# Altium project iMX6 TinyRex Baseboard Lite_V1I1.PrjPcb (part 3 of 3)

## Sheet [12] - UARTS.SchDoc
size A3; DocumentNumber: 12; SheetNumber: 12; SheetTotal: 18
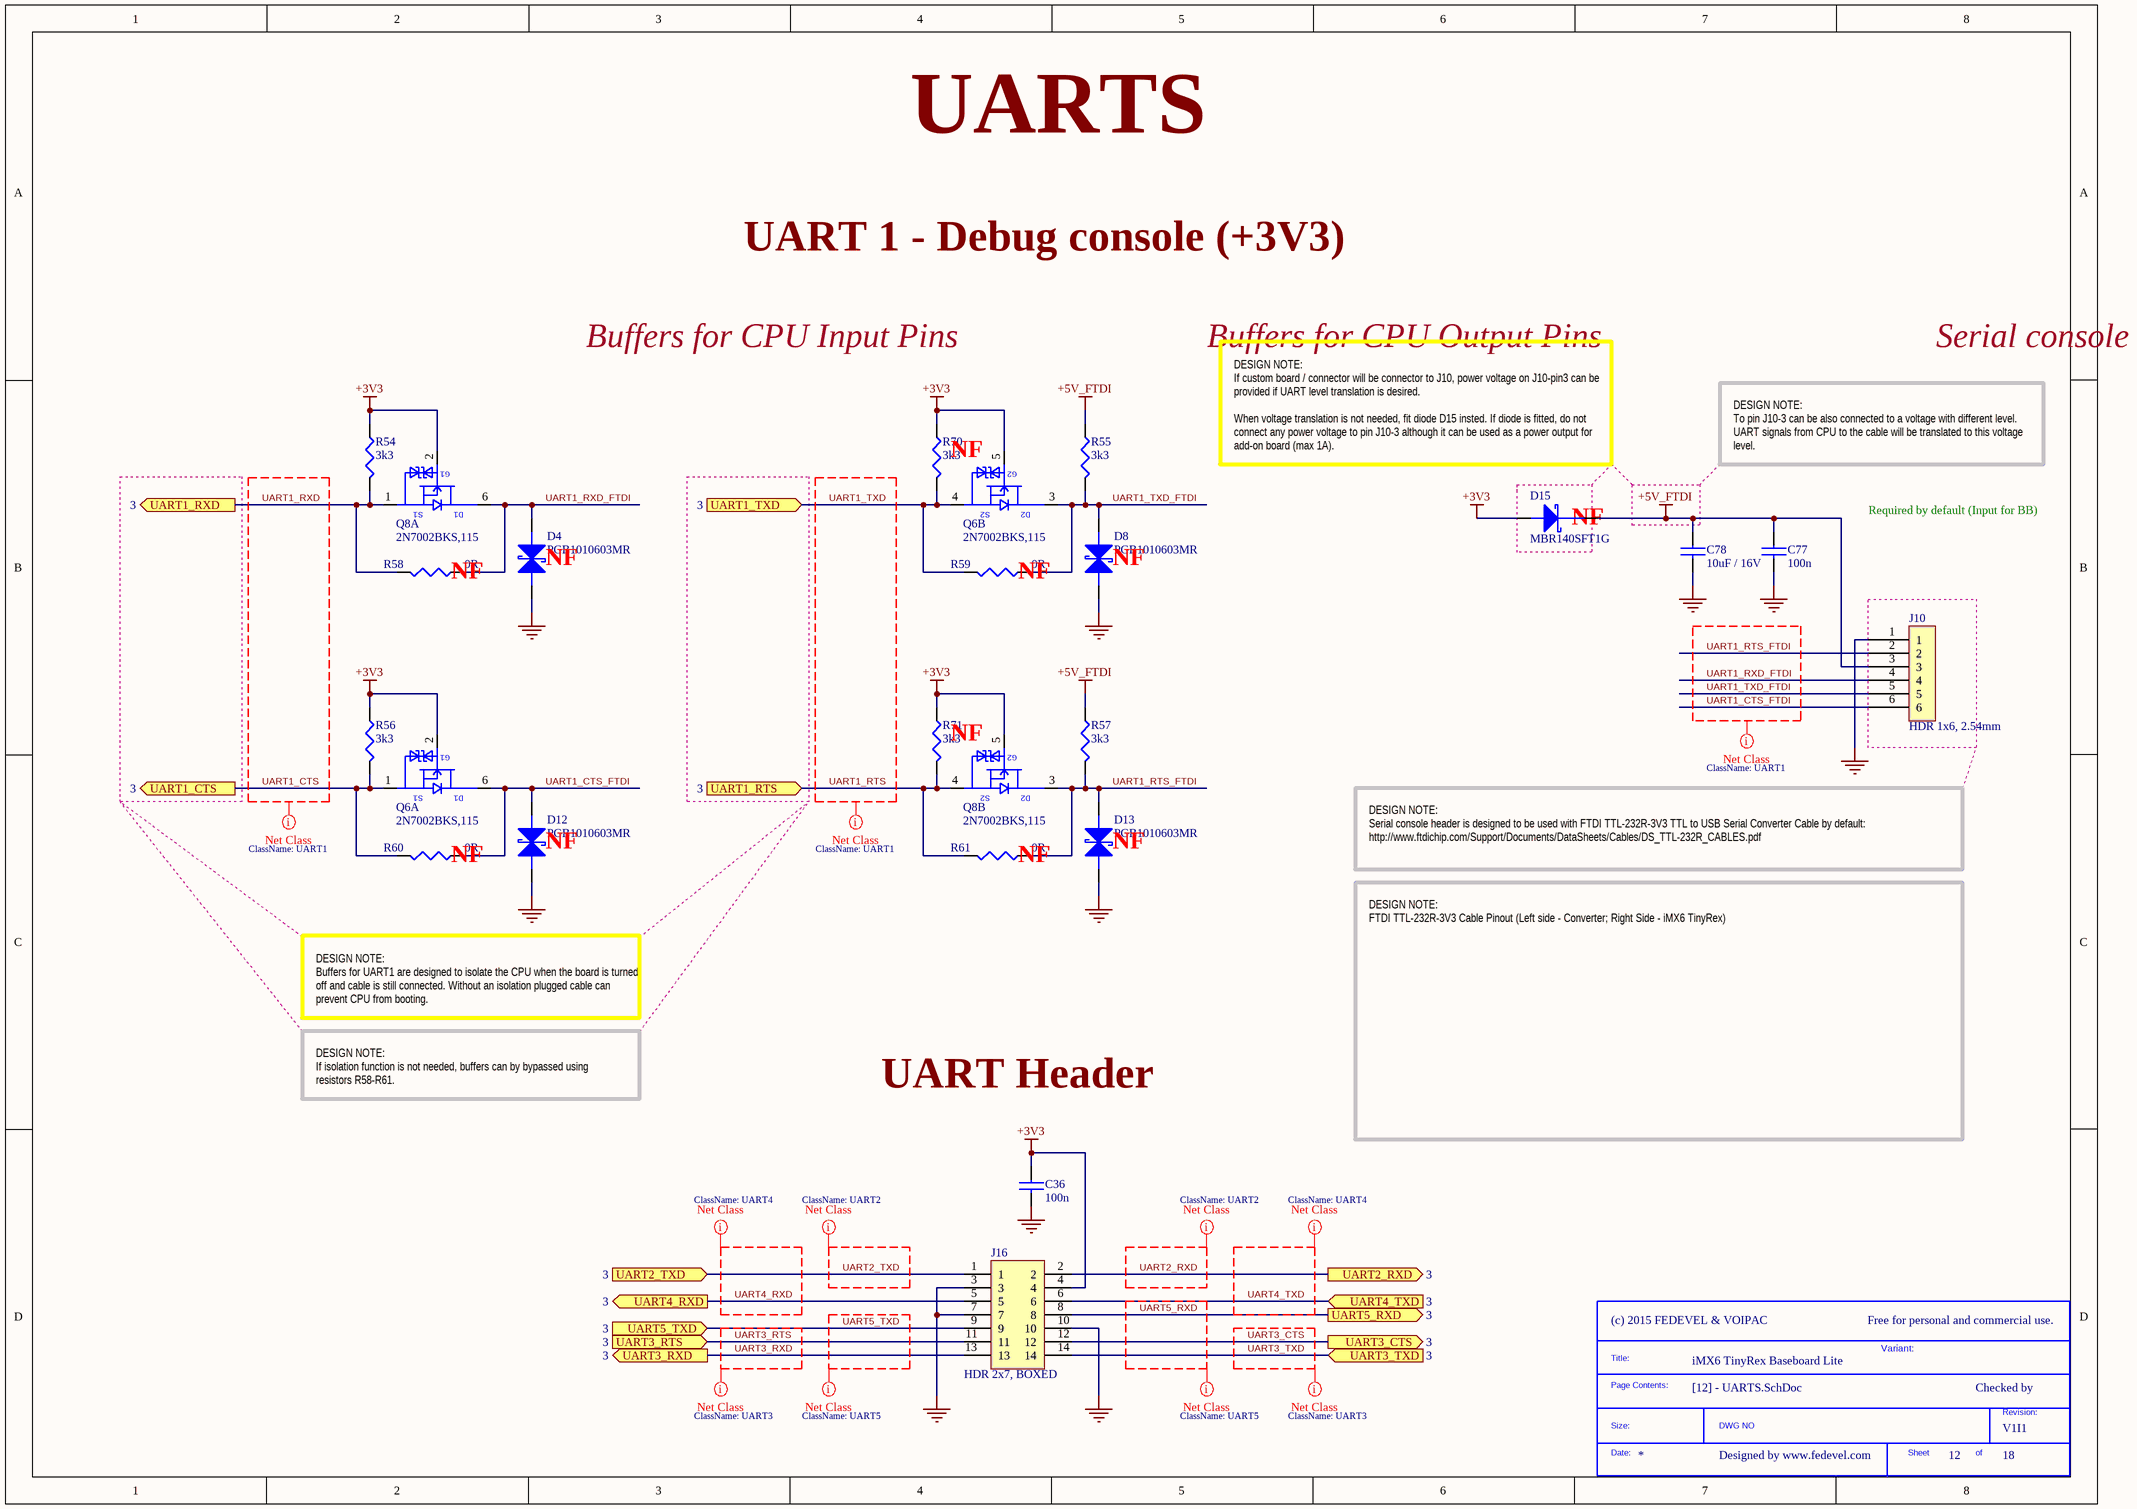
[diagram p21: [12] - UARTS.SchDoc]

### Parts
(Parts that share a designator on the sheet are numbered #1, #2 ... from top to bottom, then left to right.)
*#15  SDTitleBlock  (value not drawn)  (graphical)
C36  100n  [C0402]
C77  100n  [C0402]
C78  10uF / 16V  [C0805]
D4  PGB1010603MR  [C0603]
D8  PGB1010603MR  [C0603]
D12  PGB1010603MR  [C0603]
D13  PGB1010603MR  [C0603]
D15  MBR140SFT1G  [SOD-123FL]
J10  HDR 1x6, 2.54mm  [Hdr_1x6_2.54mm]
J16  HDR 2x7, BOXED  [HDR_2x7_2.54MM_BOXED]
Q6  2N7002BKS,115  [SOT363]  (parts A,B of 2)
Q8  2N7002BKS,115  [SOT363]  (parts A,B of 2)
R54  3k3  [R0402]
R55  3k3  [R0402]
R56  3k3  [R0402]
R57  3k3  [R0402]
R58  0R  [R0402]
R59  0R  [R0402]
R60  0R  [R0402]
R61  0R  [R0402]
R70  3k3  [R0402]
R71  3k3  [R0402]

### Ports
UART1_CTS (out, see 3), UART1_RTS (in, see 3), UART1_RXD (out, see 3), UART1_TXD (in, see 3), UART2_RXD (out, see 3), UART2_TXD (in, see 3), UART3_CTS (out, see 3), UART3_RTS (in, see 3), UART3_RXD (out, see 3), UART3_TXD (in, see 3), UART4_RXD (out, see 3), UART4_TXD (in, see 3), UART5_RXD (out, see 3), UART5_TXD (in, see 3)

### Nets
+3V3: C36.1 D15.2(Anode) J16.4 Q6.2(GATE1) Q6.5(GATE2) Q8.2(GATE1) Q8.5(GATE2) R54.2 R56.2 R70.2 R71.2
+5V_FTDI: C77.1 C78.1 D15.1(Cathode) J10.3 R55.2 R57.2
GND: C36.2 C77.2 C78.2 D4.2 D8.2 D12.2 D13.2 J10.1 J16.3 J16.7 J16.10
UART1_CTS: Q6.1(SOURCE1) R56.1 R60.1 ; port UART1_CTS
UART1_CTS_FTDI: D12.1 J10.6 Q6.6(DRAIN1) R60.2
UART1_RTS: Q8.4(SOURCE2) R61.1 R71.1 ; port UART1_RTS
UART1_RTS_FTDI: D13.1 J10.2 Q8.3(DRAIN2) R57.1 R61.2
UART1_RXD: Q8.1(SOURCE1) R54.1 R58.1 ; port UART1_RXD
UART1_RXD_FTDI: D4.1 J10.4 Q8.6(DRAIN1) R58.2
UART1_TXD: Q6.4(SOURCE2) R59.1 R70.1 ; port UART1_TXD
UART1_TXD_FTDI: D8.1 J10.5 Q6.3(DRAIN2) R55.1 R59.2
UART2_RXD: J16.2 ; port UART2_RXD
UART2_TXD: J16.1 ; port UART2_TXD
UART3_CTS: J16.12 ; port UART3_CTS
UART3_RTS: J16.11 ; port UART3_RTS
UART3_RXD: J16.13 ; port UART3_RXD
UART3_TXD: J16.14 ; port UART3_TXD
UART4_RXD: J16.5 ; port UART4_RXD
UART4_TXD: J16.6 ; port UART4_TXD
UART5_RXD: J16.8 ; port UART5_RXD
UART5_TXD: J16.9 ; port UART5_TXD

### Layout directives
net class UART3: UART3_CTS, UART3_RTS, UART3_RXD, UART3_TXD
net class UART2: UART2_RXD, UART2_TXD
net class UART5: UART5_RXD, UART5_TXD
net class UART4: UART4_RXD, UART4_TXD
net class UART1: UART1_CTS, UART1_CTS_FTDI, UART1_RTS, UART1_RTS_FTDI, UART1_RXD, UART1_RXD_FTDI, UART1_TXD, UART1_TXD_FTDI

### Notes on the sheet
- UARTS
- UART 1 - Debug console (+3V3)
- Buffers for CPU Input Pins
- Buffers for CPU Output Pins
- Serial console header
- DESIGN NOTE:
  If custom board / connector will be connector to J10, power voltage on J10-pin3 can be provided if UART level translation is desired.
  When voltage translation is not needed, fit diode D15 insted. If diode is fitted, do not connect any power voltage to pin J10-3 although it can be used as a power output for add-on board (max 1A).
- DESIGN NOTE:
  To pin J10-3 can be also connected to a voltage with different level. UART signals from CPU to the cable will be translated to this voltage level.
- Required by default (Input for BB)
- DESIGN NOTE:
  Serial console header is designed to be used with FTDI TTL-232R-3V3 TTL to USB Serial Converter Cable by default:
  http://www.ftdichip.com/Support/Documents/DataSheets/Cables/DS_TTL-232R_CABLES.pdf
- DESIGN NOTE:
  FTDI TTL-232R-3V3 Cable Pinout (Left side - Converter; Right Side - iMX6 TinyRex)
- DESIGN NOTE:
  Buffers for UART1 are designed to isolate the CPU when the board is turned off and cable is still connected. Without an isolation plugged cable can prevent CPU from booting.
- DESIGN NOTE:
  If isolation function is not needed, buffers can by bypassed using resistors R58-R61.
- UART Header
- Free for personal and commercial use.
- Variant:
- Checked by
- Designed by www.fedevel.com

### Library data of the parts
C36 C77 = C1005X5R1H104K: CAP CER .10UF 50V X5R 10% 0402; Manufacturer: TDK Corporation; Capacitance: 0.1µF; Value: 100nF; .Checked PCB: used
C78 = C2012X5R1C106M: CAP CER 10UF 16V 20% X5R 0805; Manufacturer: TDK Corporation; Manufacturer Part Number: C2012X5R1C106M/1.25; Capacitance: 10µF; .Checked PCB: used
D4 D8 D12 D13 = PGB1010603MR: SUPPRESSOR ESD 24VDC 0603 SMD; Manufacturer: Littelfuse Inc; Voltage - Reverse Standoff (Typ): 24V; Polarization: Bidirectional; .Creator: MM; .Checked PCB: used
D15 = MBR140SFT1G: DIODE SCHOTTKY 40V 1A SOD123L; Manufacturer: ON Semiconductor; Voltage - Forward (Vf) (Max) @ If: 550mV @ 1A; Speed: Fast Recovery =< 500ns, > 200mA (Io); Current - Reverse Leakage @ Vr: 500µA @ 40V; .Creator: MM
J10 = 68001-206HLF: CONN HEADER 6POS .100 STR 15AU; Manufacturer: FCI; Connector Type: Header, Unshrouded; Number of Positions: 6; Number of Positions Loaded: All; Pitch: 0.100" (2.54mm); .Creator: MM
J16 = D2514-6002-AR: CONN HEADER 14POS VERT 10GOLD; Manufacturer: 3M; Connector Type: Header, Shrouded; Number of Positions: 14; Number of Positions Loaded: All; Pitch: 0.100" (2.54mm); .Creator: MM; .Checked PCB: used
Q6 Q8 = 2N7002BKS,115: MOSFET 2N-CH 60V 0.3A 6TSSOP; Manufacturer: NXP Semiconductors; FET Type: 2 N-Channel (Dual); FET Feature: Logic Level Gate; Current - Continuous Drain (Id) @ 25°C: 300mA; Rds On (Max) @ Id, Vgs: 1.6 Ohm @ 500mA, 10V; Vgs(th) (Max) @ Id: 2.1V @ 250µA; Gate Charge (Qg) @ Vgs: 0.6nC @ 4.5V; Input Capacitance (Ciss) @ Vds: 50pF @ 10V; Power - Max: 295mW; .Creator: MM
R54-R57 R70 R71 = RC0402FR-073K3L: RES 3.30K OHM 1/16W 1% 0402 SMD; Manufacturer: Yageo; Resistance (Ohms): 3.3K; Power (Watts): 0.063W, 1/16W; .Checked PCB: used; Temperature Coefficient: ±100ppm/°C
R58-R61 = RC0402JR-070RL: RES 0.0 OHM 1/16W 0402 SMD; Manufacturer: Yageo; Resistance (Ohms): 0.0; Power (Watts): 0.063W, 1/16W; Tolerance: Jumper; .Checked PCB: used

## Sheet [13] - HEADERS, SPI.SchDoc
size A2; DocumentNumber: 13; SheetNumber: 13; SheetTotal: 18
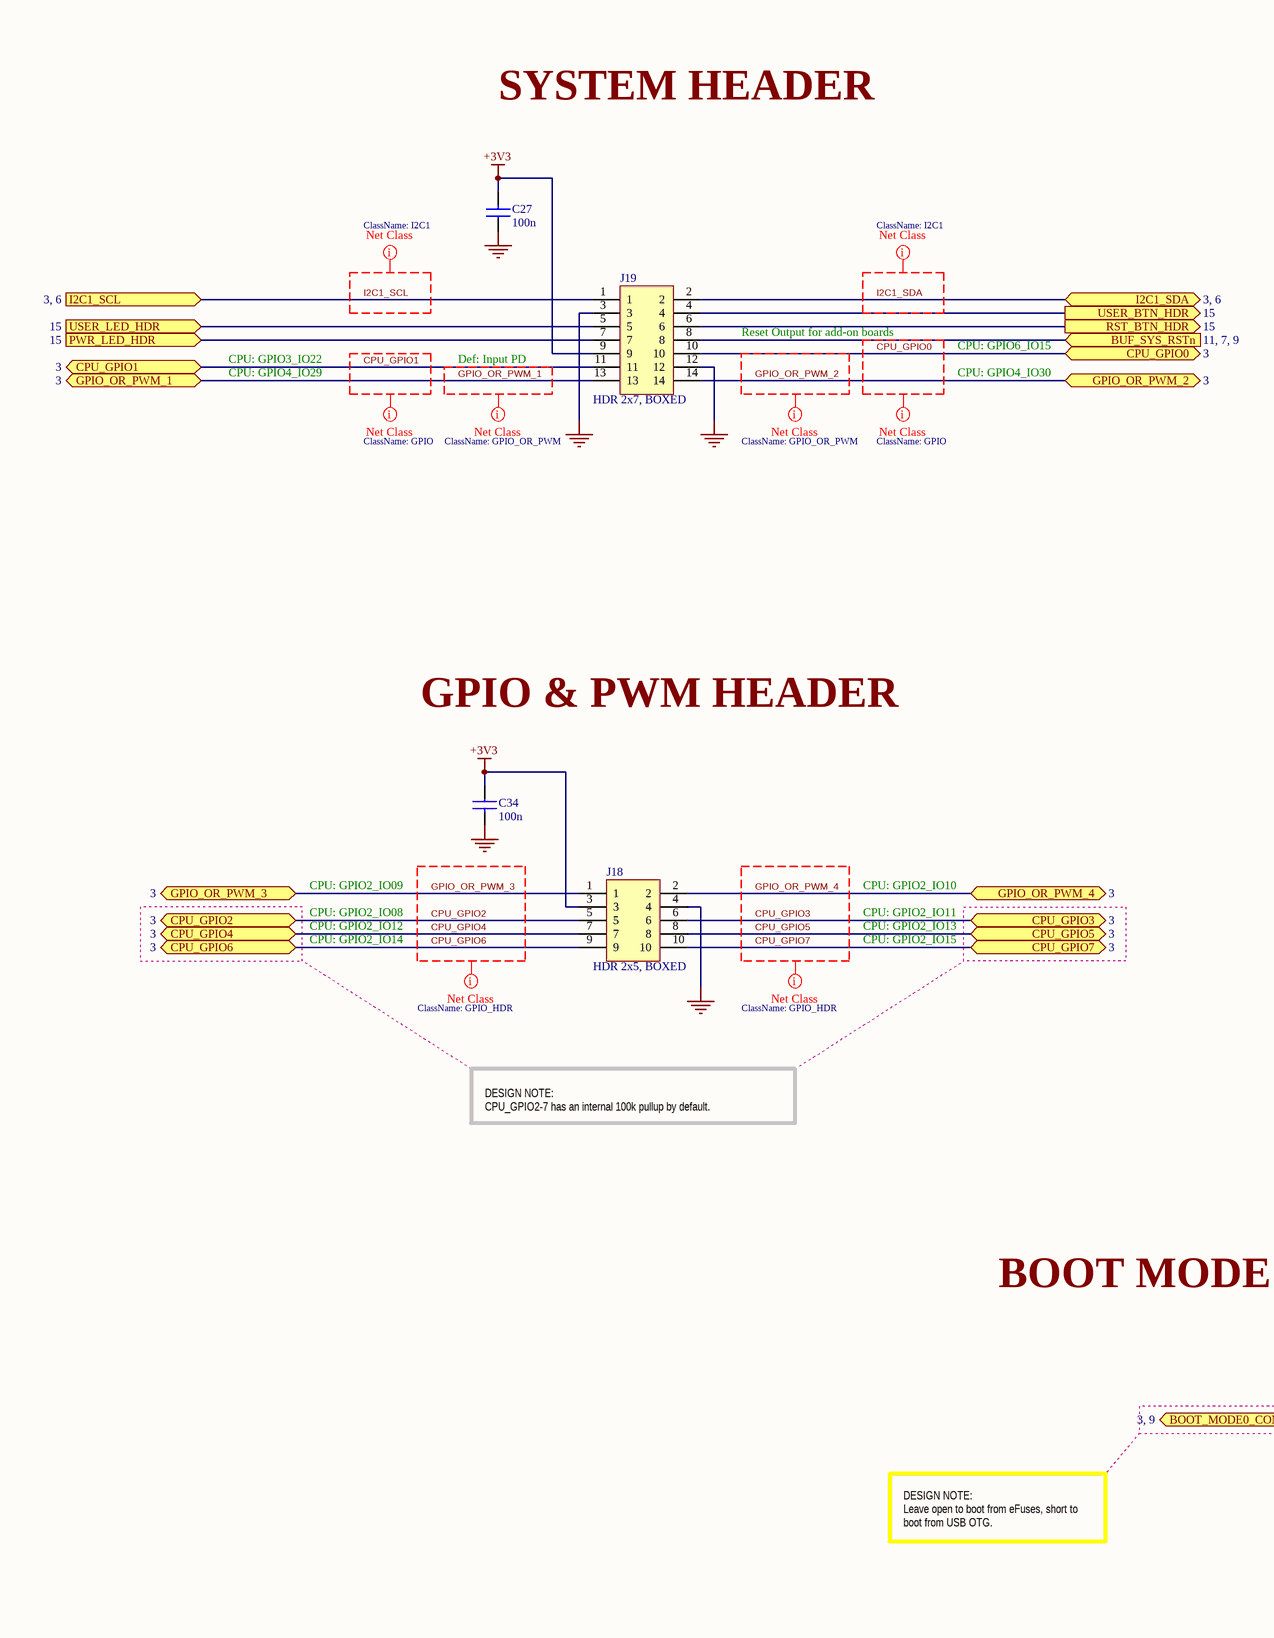
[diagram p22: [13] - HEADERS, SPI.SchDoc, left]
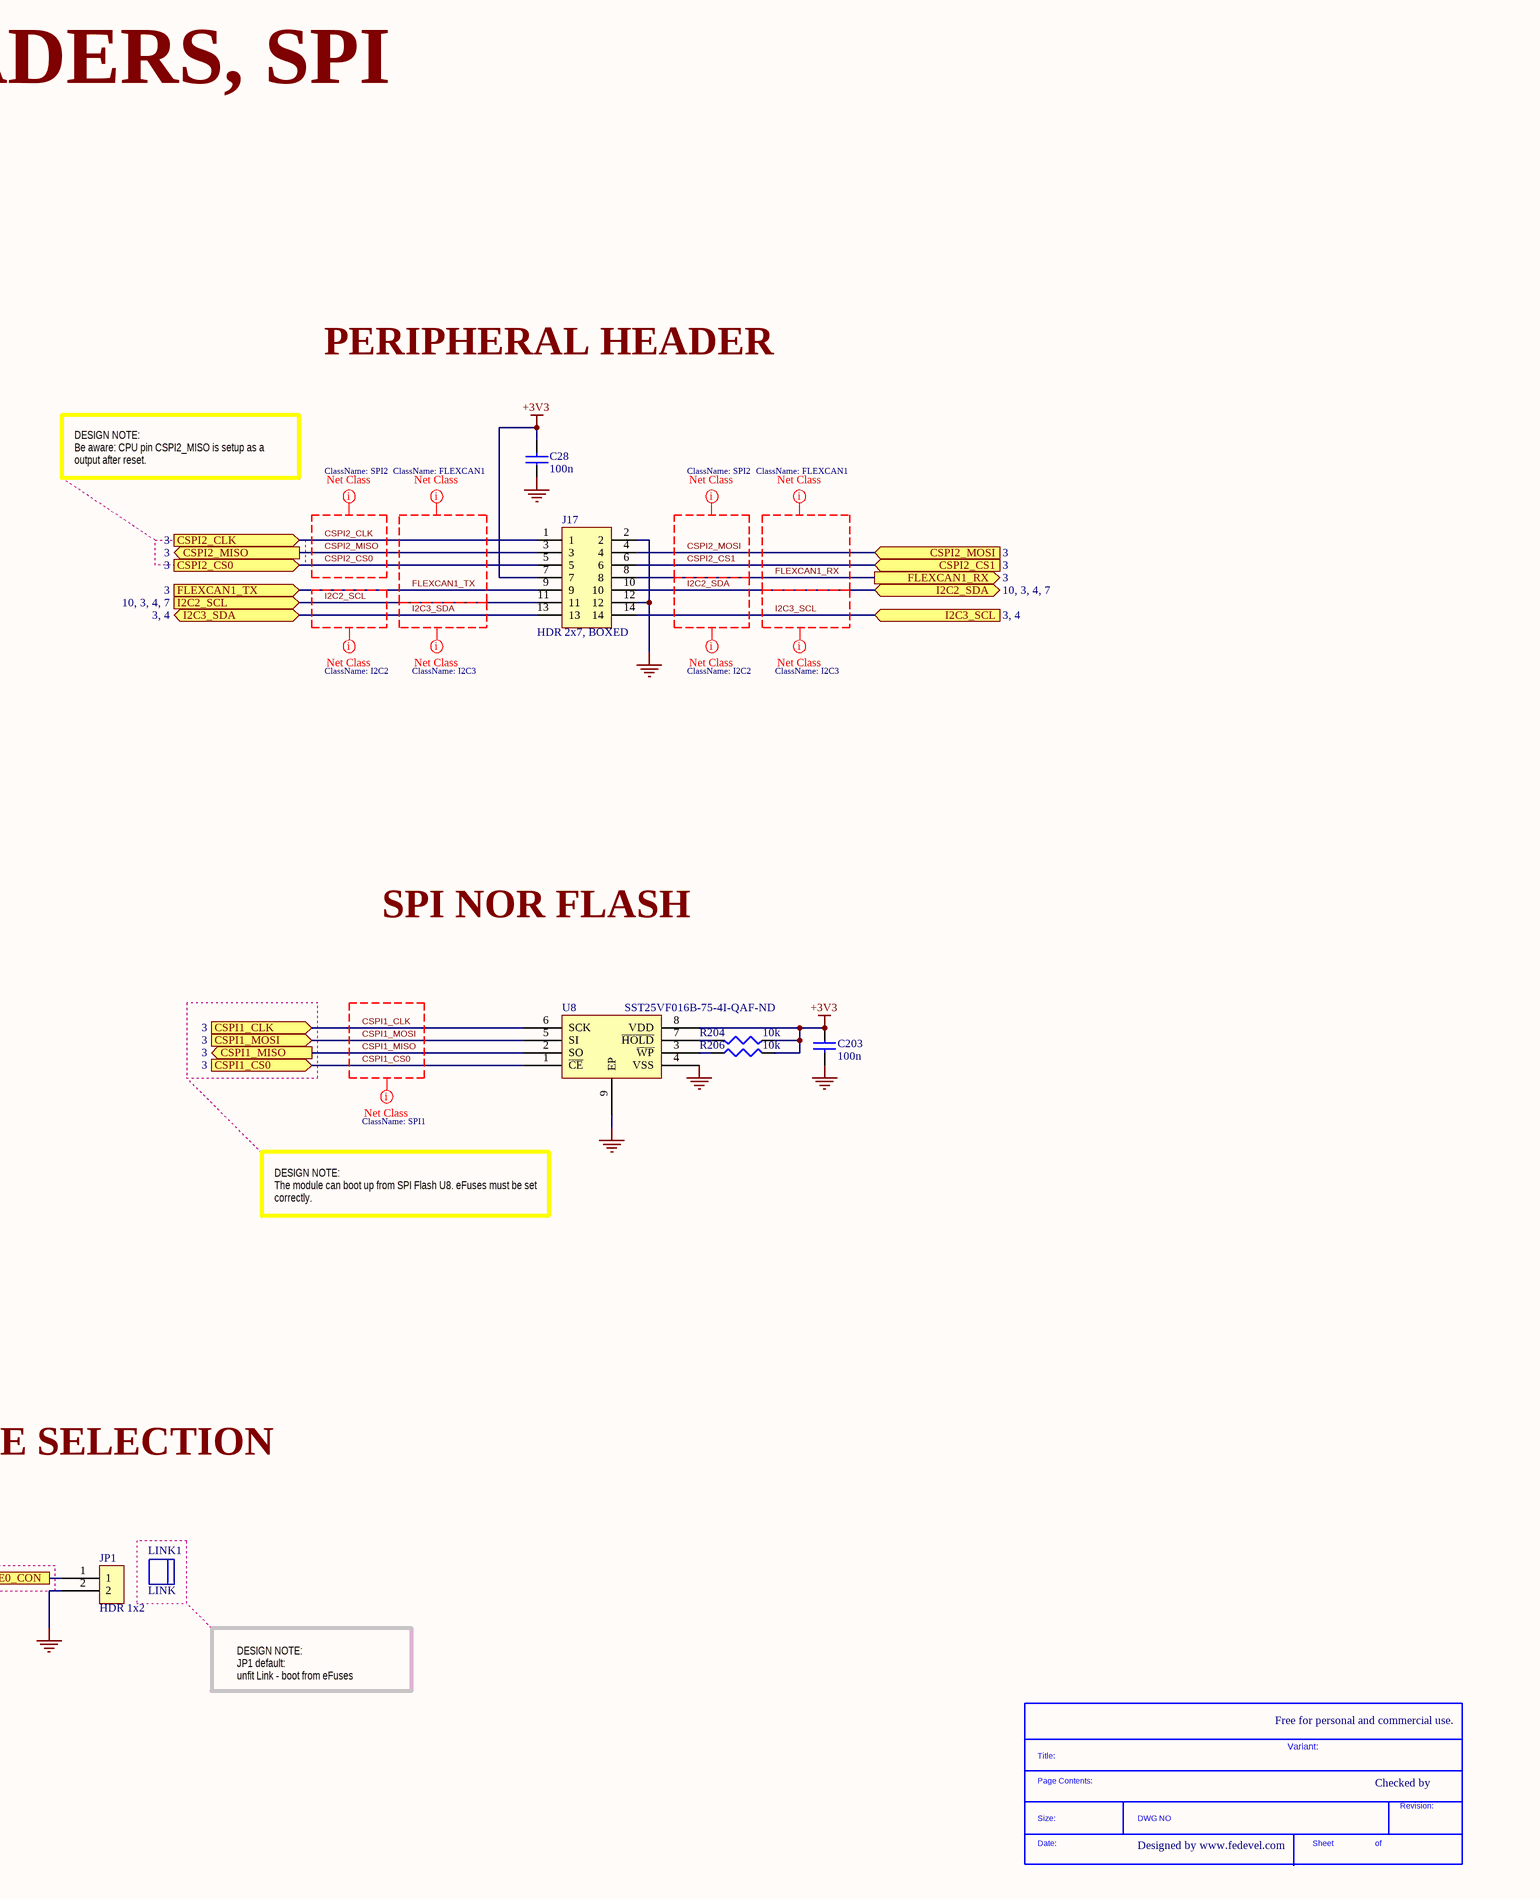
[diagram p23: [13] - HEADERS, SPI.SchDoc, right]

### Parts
(Parts that share a designator on the sheet are numbered #1, #2 ... from top to bottom, then left to right.)
*#16  SDTitleBlock  (value not drawn)  (graphical)
C27  100n  [C0402]
C28  100n  [C0402]
C34  100n  [C0402]
C203  100n  [C0402]
J17  HDR 2x7, BOXED  [HDR_2x7_2.54MM_BOXED]
J18  HDR 2x5, BOXED  [HDR_2x5_2.54mm_BOXED]
J19  HDR 2x7, BOXED  [HDR_2x7_2.54MM_BOXED]
JP1  HDR 1x2  [HDR_1x2_2.54MM]
LINK1  LINK  (mechanical)
R204  10k  [R0402]
R206  10k  [R0402]
U8  SST25VF016B-75-4I-QAF-ND  [WSON8_6X5MM]

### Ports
BOOT_MODE0_CON (see 3, 9), BUF_SYS_RSTn (see 11, 7, 9), CPU_GPIO0 (bidir, see 3), CPU_GPIO1 (bidir, see 3), CPU_GPIO2 (bidir, see 3), CPU_GPIO3 (bidir, see 3), CPU_GPIO4 (bidir, see 3), CPU_GPIO5 (bidir, see 3), CPU_GPIO6 (bidir, see 3), CPU_GPIO7 (bidir, see 3), CSPI1_CLK (in, see 3), CSPI1_CS0 (in, see 3), CSPI1_MISO (out, see 3), CSPI1_MOSI (in, see 3), CSPI2_CLK (in, see 3), CSPI2_CS0 (in, see 3), CSPI2_CS1 (in, see 3), CSPI2_MISO (out, see 3), CSPI2_MOSI (in, see 3), FLEXCAN1_RX (out, see 3), FLEXCAN1_TX (in, see 3), GPIO_OR_PWM_1 (bidir, see 3), GPIO_OR_PWM_2 (bidir, see 3), GPIO_OR_PWM_3 (bidir, see 3), GPIO_OR_PWM_4 (bidir, see 3), I2C1_SCL (see 3, 6), I2C1_SDA (bidir, see 3, 6), I2C2_SCL (see 10, 3, 4, 7), I2C2_SDA (bidir, see 10, 3, 4, 7), I2C3_SCL (see 3, 4), I2C3_SDA (bidir, see 3, 4), PWR_LED_HDR (in, see 15), RST_BTN_HDR (out, see 15), USER_BTN_HDR (out, see 15), USER_LED_HDR (in, see 15)

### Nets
+3V3: C27.2 C28.2 C34.1 C203.1 J17.7 J18.3 J19.9 R204.1 R206.2 U8.8(VDD)
GND: C27.1 C28.1 C34.2 C203.2 J17.2 J17.12 J18.4 J19.3 J19.12 JP1.2 U8.4(VSS) U8.9(EP)
BOOT_MODE0_CON: JP1.1 ; port BOOT_MODE0_CON
BUF_SYS_RSTn: J19.8 ; port BUF_SYS_RSTn
CPU_GPIO0: J19.10 ; port CPU_GPIO0
CPU_GPIO1: J19.11 ; port CPU_GPIO1
CPU_GPIO2: J18.5 ; port CPU_GPIO2
CPU_GPIO3: J18.6 ; port CPU_GPIO3
CPU_GPIO4: J18.7 ; port CPU_GPIO4
CPU_GPIO5: J18.8 ; port CPU_GPIO5
CPU_GPIO6: J18.9 ; port CPU_GPIO6
CPU_GPIO7: J18.10 ; port CPU_GPIO7
CSPI1_CLK: U8.6(SCK) ; port CSPI1_CLK
CSPI1_CS0: U8.1(~{CE}) ; port CSPI1_CS0
CSPI1_MISO: U8.2(SO) ; port CSPI1_MISO
CSPI1_MOSI: U8.5(SI) ; port CSPI1_MOSI
CSPI2_CLK: J17.1 ; port CSPI2_CLK
CSPI2_CS0: J17.5 ; port CSPI2_CS0
CSPI2_CS1: J17.6 ; port CSPI2_CS1
CSPI2_MISO: J17.3 ; port CSPI2_MISO
CSPI2_MOSI: J17.4 ; port CSPI2_MOSI
FLEXCAN1_RX: J17.8 ; port FLEXCAN1_RX
FLEXCAN1_TX: J17.9 ; port FLEXCAN1_TX
GPIO_OR_PWM_1: J19.13 ; port GPIO_OR_PWM_1
GPIO_OR_PWM_2: J19.14 ; port GPIO_OR_PWM_2
GPIO_OR_PWM_3: J18.1 ; port GPIO_OR_PWM_3
GPIO_OR_PWM_4: J18.2 ; port GPIO_OR_PWM_4
I2C1_SCL: J19.1 ; port I2C1_SCL
I2C1_SDA: J19.2 ; port I2C1_SDA
I2C2_SCL: J17.11 ; port I2C2_SCL
I2C2_SDA: J17.10 ; port I2C2_SDA
I2C3_SCL: J17.14 ; port I2C3_SCL
I2C3_SDA: J17.13 ; port I2C3_SDA
PWR_LED_HDR: J19.7 ; port PWR_LED_HDR
RST_BTN_HDR: J19.6 ; port RST_BTN_HDR
USER_BTN_HDR: J19.4 ; port USER_BTN_HDR
USER_LED_HDR: J19.5 ; port USER_LED_HDR
NetR204_2: R204.2 U8.7(~{HOLD})
NetR206_1: R206.1 U8.3(~{WP})

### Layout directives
net class SPI1: CSPI1_CLK, CSPI1_CS0, CSPI1_MISO, CSPI1_MOSI
net class GPIO: CPU_GPIO0, CPU_GPIO1
net class GPIO_OR_PWM: GPIO_OR_PWM_1, GPIO_OR_PWM_2
net class I2C3: I2C3_SCL, I2C3_SDA
net class I2C2: I2C2_SCL, I2C2_SDA
net class SPI2: CSPI2_CLK, CSPI2_CS0, CSPI2_CS1, CSPI2_MISO, CSPI2_MOSI
net class GPIO_HDR: CPU_GPIO2, CPU_GPIO3, CPU_GPIO4, CPU_GPIO5, CPU_GPIO6, CPU_GPIO7, GPIO_OR_PWM_3, GPIO_OR_PWM_4
net class I2C1: I2C1_SCL, I2C1_SDA
net class FLEXCAN1: FLEXCAN1_RX, FLEXCAN1_TX

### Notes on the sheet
- HEADERS, SPI
- SYSTEM HEADER
- PERIPHERAL HEADER
- DESIGN NOTE:
  Be aware: CPU pin CSPI2_MISO is setup as a output after reset.
- CPU: GPIO4_IO29
- CPU: GPIO3_IO22
- Def: Input PD
- Reset Output for add-on boards
- CPU: GPIO6_IO15
- CPU: GPIO4_IO30
- GPIO & PWM HEADER
- SPI NOR FLASH
- CPU: GPIO2_IO09
- CPU: GPIO2_IO08
- CPU: GPIO2_IO10
- CPU: GPIO2_IO11
- CPU: GPIO2_IO12
- CPU: GPIO2_IO14
- CPU: GPIO2_IO13
- CPU: GPIO2_IO15
- DESIGN NOTE:
  The module can boot up from SPI Flash U8. eFuses must be set correctly.
- DESIGN NOTE:
  CPU_GPIO2-7 has an internal 100k pullup by default.
- BOOT MODE SELECTION
- DESIGN NOTE:
  Leave open to boot from eFuses, short to boot from USB OTG.
- DESIGN NOTE:
  JP1 default:
  unfit Link - boot from eFuses
- Free for personal and commercial use.
- Variant:
- Checked by
- Designed by www.fedevel.com

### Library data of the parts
C27 C28 C34 C203 = C1005X5R1H104K: as C36 on sheet [12] - UARTS
J17 J19 = D2514-6002-AR: as J16 on sheet [12] - UARTS
J18 = D2510-6002-AR: CONN HEADER 10POS VERT 10GOLD; Manufacturer: 3M; Connector Type: Header, Shrouded; Number of Positions: 10; Number of Positions Loaded: All; Pitch: 0.100" (2.54mm); .Creator: MM; .Checked PCB: used
JP1 = 68001-202HLF: BERGSTIK II .100" SR STRAIGHT; Manufacturer: FCI; Connector Type: Header, Unshrouded; Number of Positions: 2; Number of Positions Loaded: All; Pitch: 0.100" (2.54mm); .Checked PCB: used
LINK1 = QPC02SXGN-RC: CONN JUMPER SHORTING .100" GOLD; Manufacturer: Sullins Connector Solutions; Gender: Female Sockets; Number of Positions or Pins (Grid): 2 (1 x 2); Pitch: 0.100" (2.54mm); .Checked SCH: used
R204 R206 = RC0402FR-0710KL: RES 10.0K OHM 1/16W 1% 0402 SMD; Manufacturer: Yageo; Power (Watts): 0.063W, 1/16W; .Checked PCB: used; Temperature Coefficient: ±100ppm/°C
U8 = SST25VF016B-75-4I-QAF: IC FLASH 16MBIT 75MHZ 8WSON; Manufacturer: Microchip Technology; Memory Size: 16M (2M x 8); Interface: SPI Serial; Voltage - Supply: 2.7 V ~ 3.6 V; .Creator: MM; .Checked PCB: used

## Sheet [14] - PWR 5V, 3V3, 2V5.SchDoc
size A2; DocumentNumber: 14; SheetNumber: 14; SheetTotal: 18
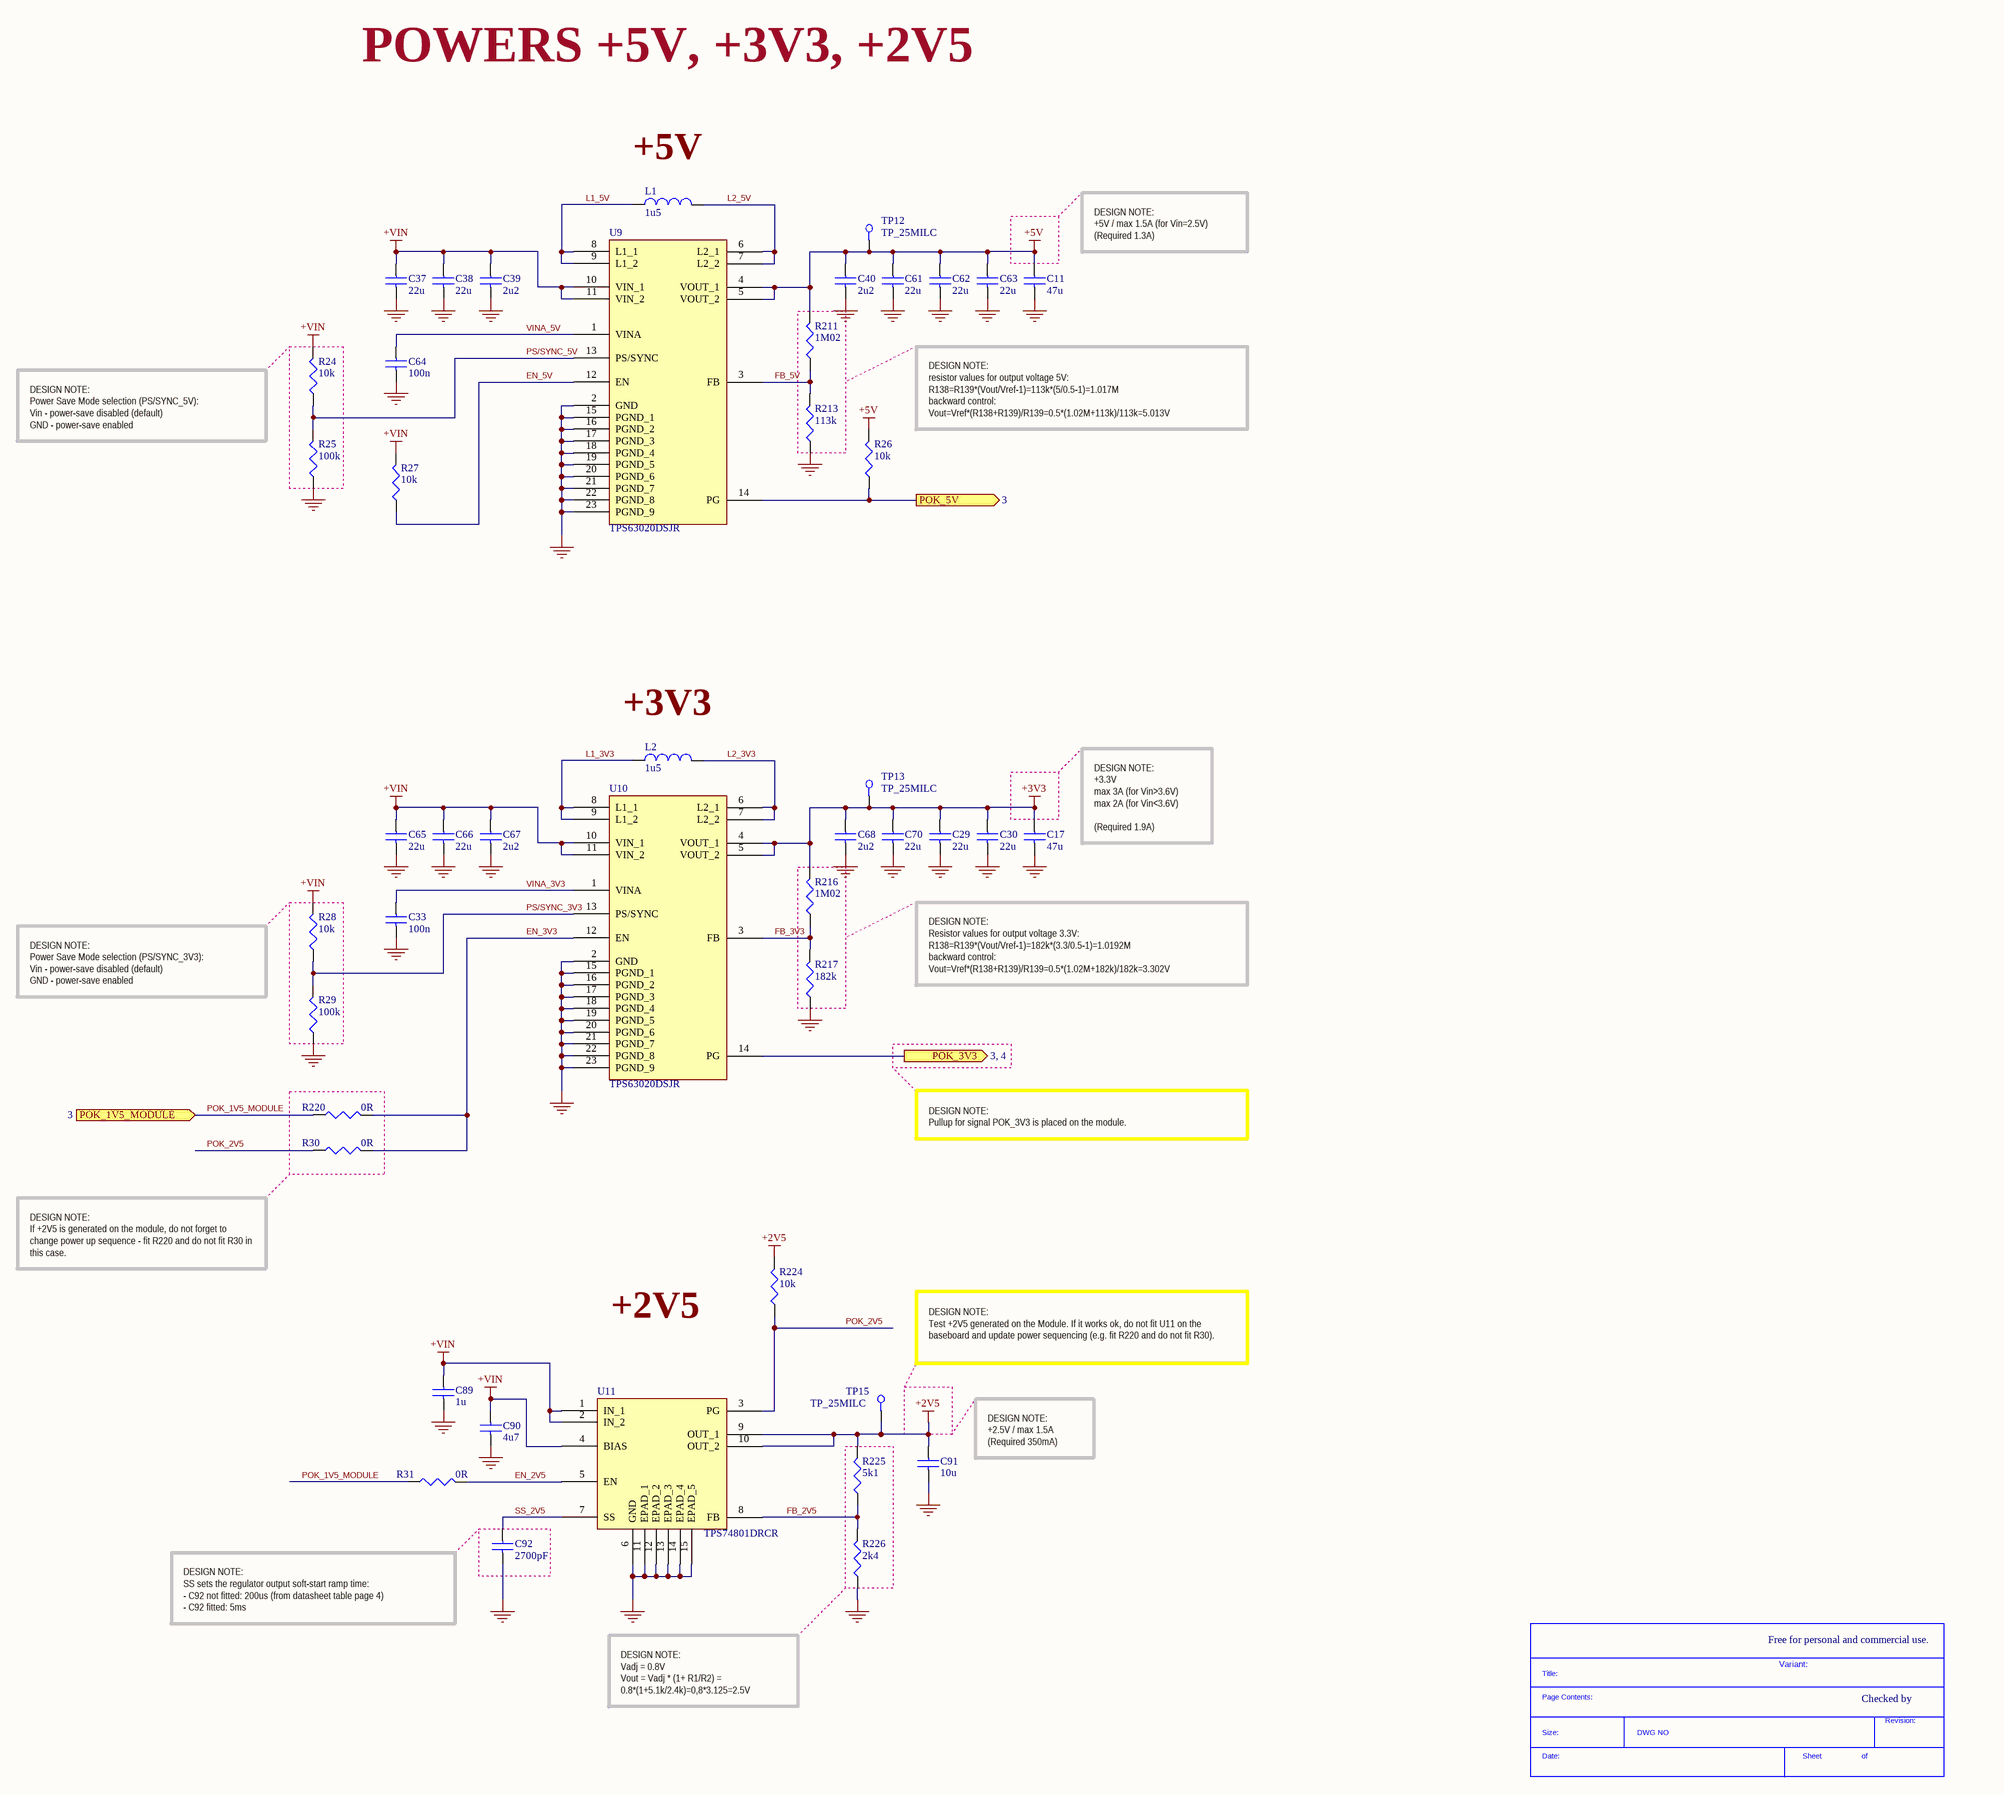
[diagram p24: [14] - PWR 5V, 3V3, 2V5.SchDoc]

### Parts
(Parts that share a designator on the sheet are numbered #1, #2 ... from top to bottom, then left to right.)
*#17  SDTitleBlock  (value not drawn)  (graphical)
C11  47u  [C0805]
C17  47u  [C0805]
C29  22u  [C0603]
C30  22u  [C0603]
C33  100n  [C0402]
C37  22u  [C0603]
C38  22u  [C0603]
C39  2u2  [C0402]
C40  2u2  [C0402]
C61  22u  [C0603]
C62  22u  [C0603]
C63  22u  [C0603]
C64  100n  [C0402]
C65  22u  [C0603]
C66  22u  [C0603]
C67  2u2  [C0402]
C68  2u2  [C0402]
C70  22u  [C0603]
C89  1u  [C0402]
C90  4u7  [C0402]
C91  10u  [C0603]
C92  2700pF  [C0402]
L1  1u5  [IHLP_204MILX216MIL]
L2  1u5  [IHLP_204MILX216MIL]
R24  10k  [R0402]
R25  100k  [R0402]
R26  10k  [R0402]
R27  10k  [R0402]
R28  10k  [R0402]
R29  100k  [R0402]
R30  0R  [R0402]
R31  0R  [R0402]
R211  1M02  [R0402]
R213  113k  [R0402]
R216  1M02  [R0402]
R217  182k  [R0402]
R220  0R  [R0402]
R224  10k  [R0402]
R225  5k1  [R0402]
R226  2k4  [R0402]
TP12  TP_25MILC  [TP_25C]  (no BOM)
TP13  TP_25MILC  [TP_25C]  (no BOM)
TP15  TP_25MILC  [TP_25C]  (no BOM)
U9  TPS63020DSJR  [DSJ (R-PVSON-N14)]
U10  TPS63020DSJR  [DSJ (R-PVSON-N14)]
U11  TPS74801DRCR  [DRC (S-PVSON-N10)]

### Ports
POK_1V5_MODULE (in, see 3), POK_3V3 (see 3, 4), POK_5V (out, see 3)

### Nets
+2V5: C91.1 R224.2 R225.2 TP15.1 U11.9(OUT_1) U11.10(OUT_2)
+3V3: C17.1 C29.1 C30.1 C68.1 C70.1 R216.2 TP13.1 U10.4(VOUT_1) U10.5(VOUT_2)
+5V: C11.1 C40.1 C61.1 C62.1 C63.1 R26.2 R211.2 TP12.1 U9.4(VOUT_1) U9.5(VOUT_2)
+VIN: C37.1 C38.1 C39.1 C65.1 C66.1 C67.1 C89.1 C90.1 R24.2 R27.2 R28.2 U9.10(VIN_1) U9.11(VIN_2) U10.10(VIN_1) U10.11(VIN_2) U11.1(IN_1) U11.2(IN_2) U11.4(BIAS)
GND: C11.2 C17.2 C29.2 C30.2 C33.2 C37.2 C38.2 C39.2 C40.2 C61.2 C62.2 C63.2 C64.2 C65.2 C66.2 C67.2 C68.2 C70.2 C89.2 C90.2 C91.2 C92.2 R25.1 R29.1 R213.1 R217.1 R226.1 U9.2(GND) U9.15(PGND_1) U9.16(PGND_2) U9.17(PGND_3) U9.18(PGND_4) U9.19(PGND_5) U9.20(PGND_6) U9.21(PGND_7) U9.22(PGND_8) U9.23(PGND_9) U10.2(GND) U10.15(PGND_1) U10.16(PGND_2) U10.17(PGND_3) U10.18(PGND_4) U10.19(PGND_5) U10.20(PGND_6) U10.21(PGND_7) U10.22(PGND_8) U10.23(PGND_9) U11.6(GND) U11.11(EPAD_1) U11.12(EPAD_2) U11.13(EPAD_3) U11.14(EPAD_4) U11.15(EPAD_5)
EN_2V5: R31.2 U11.5(EN)
EN_3V3: R30.2 R220.2 U10.12(EN)
EN_5V: R27.1 U9.12(EN)
FB_2V5: R225.1 R226.2 U11.8(FB)
FB_3V3: R216.1 R217.2 U10.3(FB)
FB_5V: R211.1 R213.2 U9.3(FB)
L1_3V3: L2.1 U10.8(L1_1) U10.9(L1_2)
L1_5V: L1.1 U9.8(L1_1) U9.9(L1_2)
L2_3V3: L2.2 U10.6(L2_1) U10.7(L2_2)
L2_5V: L1.2 U9.6(L2_1) U9.7(L2_2)
POK_1V5_MODULE: R31.1 R220.1 ; port POK_1V5_MODULE
POK_2V5: R30.1 R224.1 U11.3(PG)
POK_3V3: U10.14(PG) ; port POK_3V3
POK_5V: R26.1 U9.14(PG) ; port POK_5V
PS/SYNC_3V3: R28.1 R29.2 U10.13(PS/SYNC)
PS/SYNC_5V: R24.1 R25.2 U9.13(PS/SYNC)
SS_2V5: C92.1 U11.7(SS)
VINA_3V3: C33.1 U10.1(VINA)
VINA_5V: C64.1 U9.1(VINA)

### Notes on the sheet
- POWERS +5V, +3V3, +2V5
- (near L1) +5V
- DESIGN NOTE:
  +5V / max 1.5A (for Vin=2.5V)
  (Required 1.3A)
- DESIGN NOTE:
  Power Save Mode selection (PS/SYNC_5V):
  Vin - power-save disabled (default)
  GND - power-save enabled
- DESIGN NOTE:
  resistor values for output voltage 5V:
  R138=R139*(Vout/Vref-1)=113k*(5/0.5-1)=1.017M
  backward control:
  Vout=Vref*(R138+R139)/R139=0.5*(1.02M+113k)/113k=5.013V
- (near L2) +3V3
- DESIGN NOTE:
  +3.3V
  max 3A (for Vin>3.6V)
  max 2A (for Vin<3.6V)
  (Required 1.9A)
- DESIGN NOTE:
  Power Save Mode selection (PS/SYNC_3V3):
  Vin - power-save disabled (default)
  GND - power-save enabled
- DESIGN NOTE:
  Resistor values for output voltage 3.3V:
  R138=R139*(Vout/Vref-1)=182k*(3.3/0.5-1)=1.0192M
  backward control:
  Vout=Vref*(R138+R139)/R139=0.5*(1.02M+182k)/182k=3.302V
- DESIGN NOTE:
  Pullup for signal POK_3V3 is placed on the module.
- DESIGN NOTE:
  If +2V5 is generated on the module, do not forget to change power up sequence - fit R220 and do not fit R30 in this case.
- +2V5
- DESIGN NOTE:
  Test +2V5 generated on the Module. If it works ok, do not fit U11 on the baseboard and update power sequencing (e.g. fit R220 and do not fit R30).
- DESIGN NOTE:
  +2.5V / max 1.5A
  (Required 350mA)
- DESIGN NOTE:
  SS sets the regulator output soft-start ramp time:
  - C92 not fitted: 200us (from datasheet table page 4)
  - C92 fitted: 5ms
- Free for personal and commercial use.
- DESIGN NOTE:
  Vadj = 0.8V
  Vout = Vadj * (1+ R1/R2) = 0.8*(1+5.1k/2.4k)=0,8*3.125=2.5V
- Variant:
- Checked by

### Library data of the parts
C11 C17 = JMK212BJ476MG-T: CAP CER 47UF 6.3V 20% X5R 0805; Manufacturer: Taiyo Yuden; Capacitance: 47µF; .Creator: MM
C29 C30 C37 C38 C61-C63 C65 C66 C70 = C1608X5R0J226M080AC: CAP CER 22UF 6.3V 20% X5R 0603; Manufacturer: TDK Corporation; Capacitance: 22µF; .Creator: MM
C33 C64 = C1005X5R1H104K: as C36 on sheet [12] - UARTS
C39 C40 C67 C68 = C1005X5R1A225K: CAP CER 2.2UF 10V 10% X5R 0402; Manufacturer: TDK Corporation; Capacitance: 2.2µF; .Checked PCB: used
C89 = C1005X5R1C105K: CAP CER 1.0UF 16V X5R 0402; Manufacturer: TDK Corporation; Capacitance: 1.0µF; Value: 1uF; .Checked PCB: used; Tolerance: ±10%
C90 = C1005X5R1A475M: CAP CER 4.7UF 10V 20% X5R 0402; Manufacturer: TDK Corporation; Capacitance: 4.7µF; .Checked PCB: used
C91 = C1608X5R0J106M: CAP CER 10UF 6.3V X5R 20% 0603; Manufacturer: TDK Corporation; Capacitance: 10µF; Value: 10µF; .Checked PCB: used
C92 = GRM155R71H272KA01D: CAP CER 2700PF 50V 10% X7R 0402; Manufacturer: Murata Electronics North America; .Checked PCB: used
L1 L2 = IHLP2020CZER1R5M11: FIXED IND 1.5UH 7.5A 18.5 MOHM; Manufacturer: Vishay Dale; Type: Molded; Inductance: 1.5µH; Tolerance: ±20%; Current - Saturation: 7A; Shielding: Shielded; DC Resistance (DCR): 18.5 mOhm Max; Frequency - Self Resonant: 39MHz; Frequency - Test: 100kHz; .Creator: MM
R24 R26-R28 R224 = RC0402FR-0710KL: as R204 on sheet [13] - HEADERS, SPI
R25 R29 = RMCF0402FT100K: RES 100K OHM 1/16W 1% 0402 SMD; Manufacturer: Stackpole Electronics Inc; Power (Watts): 0.063W, 1/16W; .Checked PCB: used; Temperature Coefficient: ±100ppm/°C
R30 R31 R220 = RC0402JR-070RL: as R58-R61 on sheet [12] - UARTS
R211 R216 = CRCW04021M02FKED: RES 1.02M OHM 1/16W 1% 0402 SMD; Manufacturer: Vishay Dale; Power (Watts): 0.063W, 1/16W; Temperature Coefficient: ±100ppm/°C; .Creator: MM
R213 = CRCW0402113KFKED: RES 113K OHM 1/16W 1% 0402 SMD; Manufacturer: Vishay Dale; Power (Watts): 0.063W, 1/16W; Temperature Coefficient: ±100ppm/°C; .Creator: MM
R217 = CRCW0402182KFKED: RES 182K OHM 1/16W 1% 0402 SMD; Manufacturer: Vishay Dale; Power (Watts): 0.063W, 1/16W; Temperature Coefficient: ±100ppm/°C; .Creator: MM
R225 = RC0402FR-075K1L: RES 5.10K OHM 1/16W 1% 0402 SMD; Manufacturer: Yageo; Resistance (Ohms): 5.1K; Power (Watts): 0.063W, 1/16W; .Checked PCB: RF; Temperature Coefficient: ±100ppm/°C
R226 = CRCW04022K40FKED: RES 2.40K OHM 1/16W 1% 0402 SMD; Manufacturer: Vishay Dale; Resistance (Ohms): 2.4K; Power (Watts): 0.063W, 1/16W; Temperature Coefficient: ±100ppm/°C; .Checked PCB: used
TP12 TP13 TP15 = TP_25MILC: Test Point 25mil
U9 U10 = TPS63020DSJR: IC REG BUCK BST SYNC ADJ 14VSON; Manufacturer: Texas Instruments; Output Type: Adjustable; Number of Outputs: 1; Voltage - Output: 1.2 V ~ 5.5 V; Voltage - Input: 1.8 V ~ 5.5 V; Frequency - Switching: 2.4MHz; Current - Output: 3A; Synchronous Rectifier: Yes; .Creator: MM
U11 = TPS74801DRCR: IC REG LDO ADJ 1.5A 10SON; Manufacturer: Texas Instruments; Number of Regulators: 1; Regulator Topology: Positive Adjustable; Voltage - Input: 0.8 V ~ 5.5 V; Voltage - Output: 0.8 V ~ 3.6 V; Voltage - Dropout (Typical): 0.06V @ 1.5A; Current - Output: 1.5A (Max); Current - Limit (Min): 2A; .Creator: MM; .Checked PCB: used

## Sheet [17] - REVISION HISTORY.SchDoc
size A3; DocumentNumber: 17; SheetNumber: 17; SheetTotal: 18
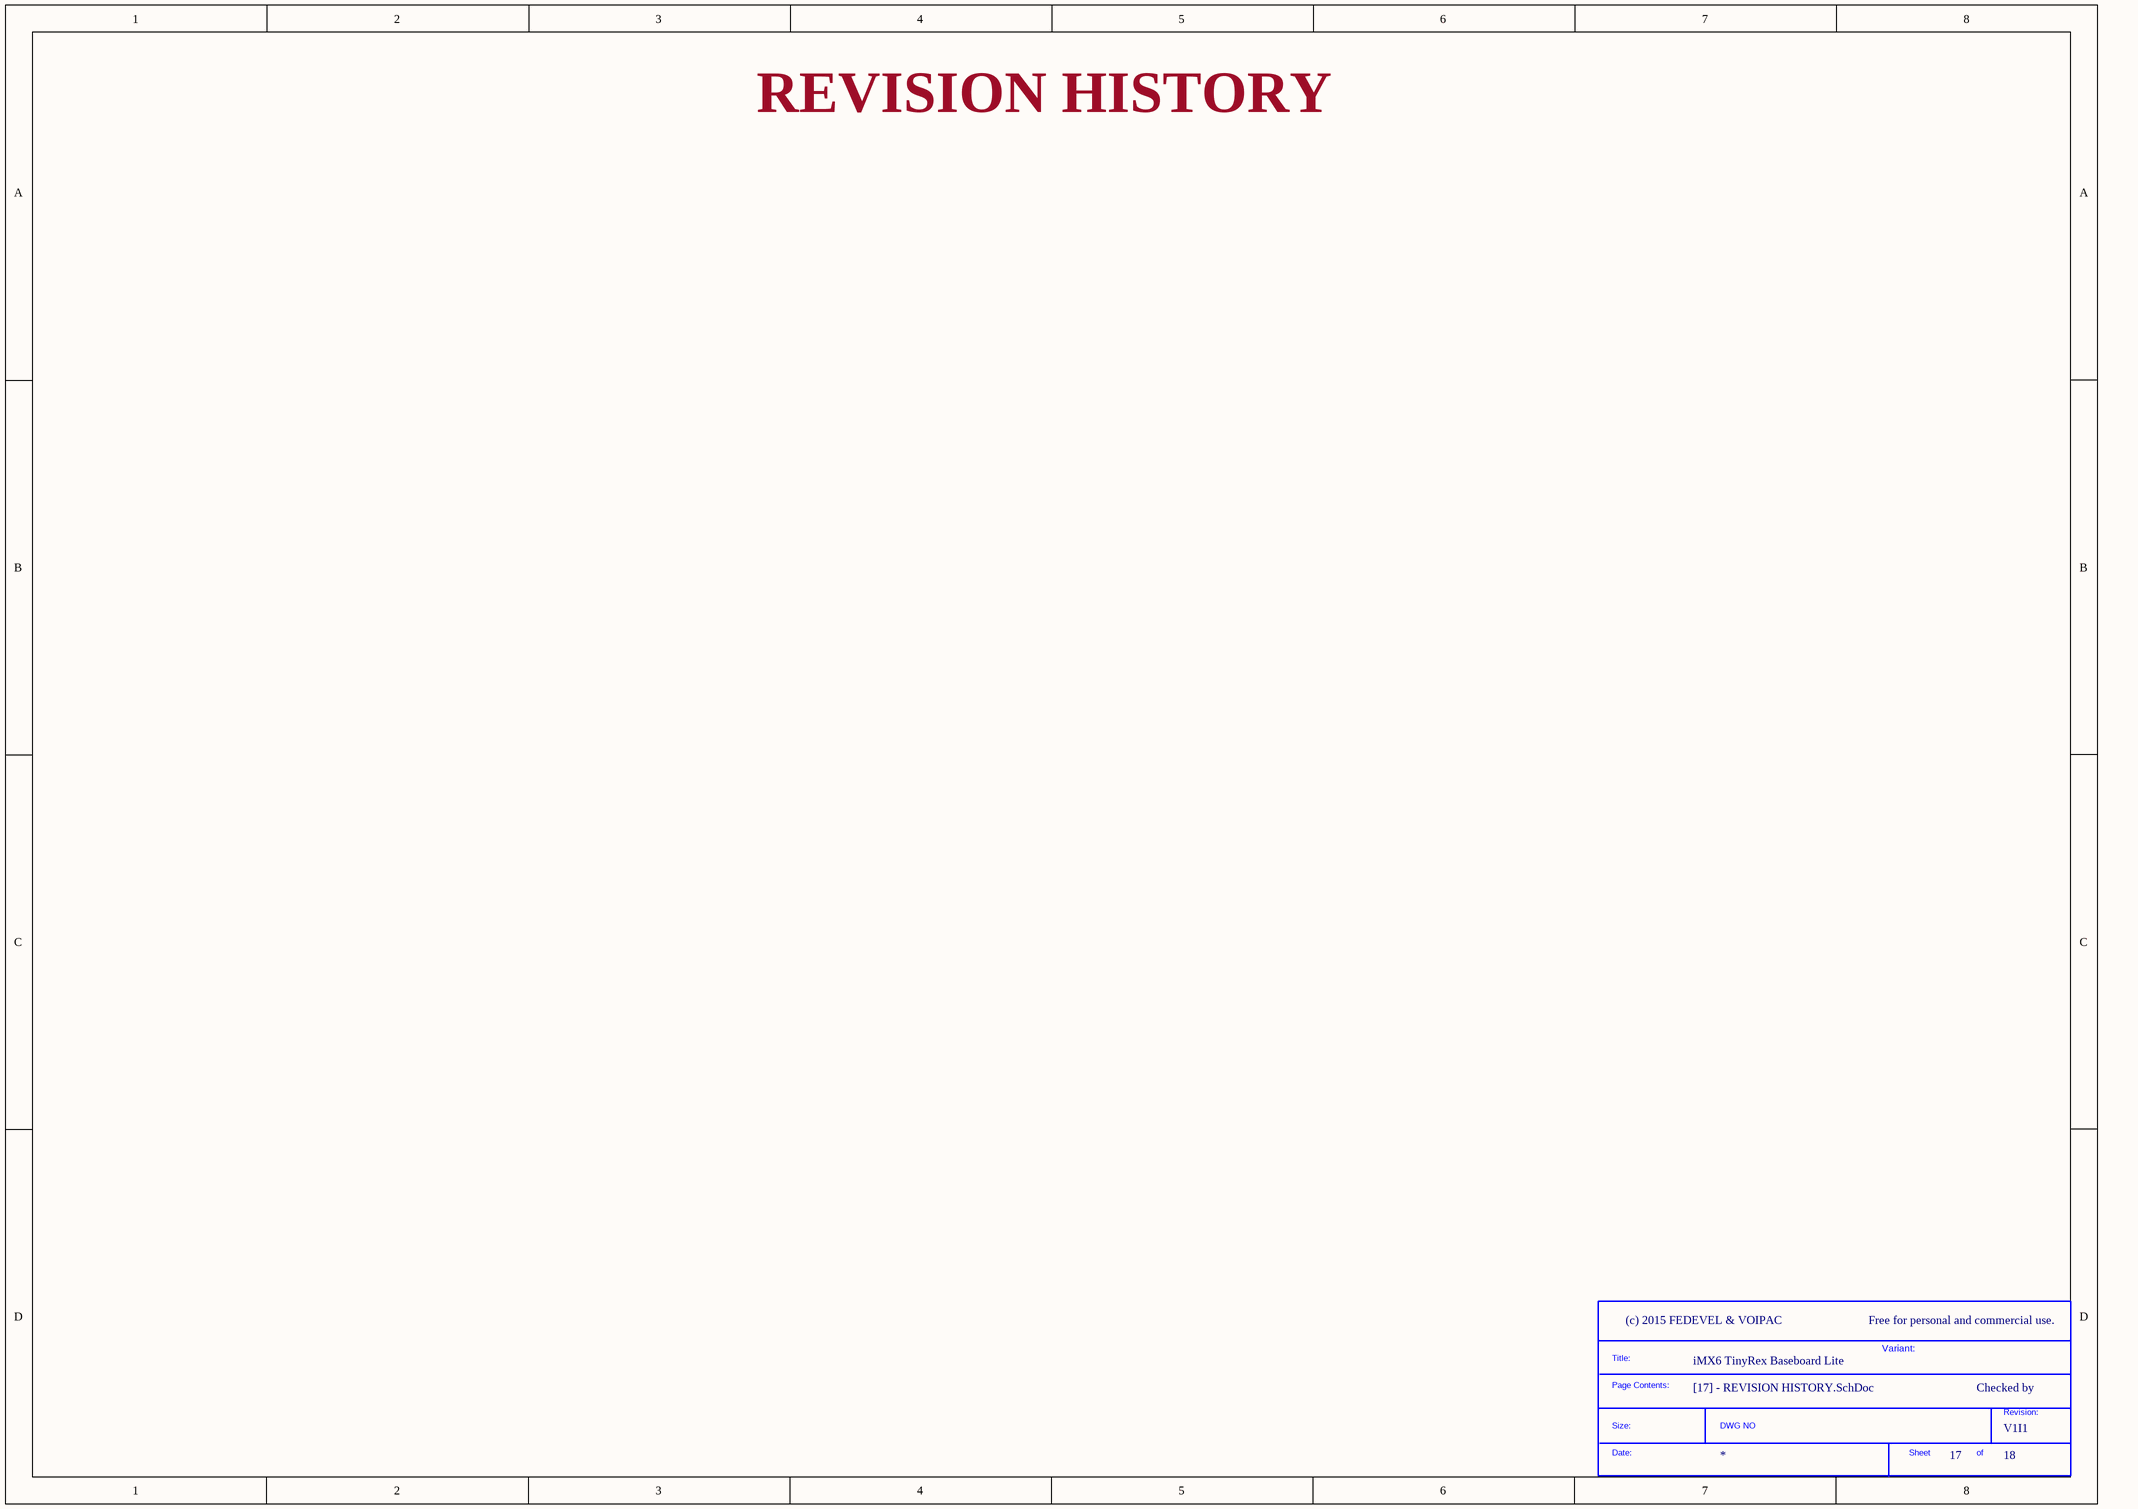
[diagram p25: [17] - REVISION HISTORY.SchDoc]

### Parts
(Parts that share a designator on the sheet are numbered #1, #2 ... from top to bottom, then left to right.)
*#18  SDTitleBlock  (value not drawn)  (graphical)

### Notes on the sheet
- REVISION HISTORY
- Free for personal and commercial use.
- Variant:
- Checked by

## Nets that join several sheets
+2V5: [03] - CONNECTORS (C14.1 C232.1 J3.48 J3.58), [14] - PWR 5V, 3V3, 2V5 (6 pins)
+3V3: [15] - PWR IN, LEDS, BUTTONS, MECH (D5.2 D14.2 R140.2 R147.2), [04] - VIDEO INPUT (6 pins), [05] - HDMI INPUT (D7.2 R11.2 R12.2 R13.2), [06] - HDMI OUTPUT (5 pins), [07] - PCIE MINI (FB9.1 R10.2 R37.2), [09] - USB (11 pins), [08] - ETHERNET (C115.1 J5.10 J5.12), [03] - CONNECTORS (8 pins), [10] - SATA, CSI (R138.1), [11] - SD CARD, BUFFERS (8 pins), [12] - UARTS (11 pins), [13] - HEADERS, SPI (10 pins), [14] - PWR 5V, 3V3, 2V5 (9 pins)
+5V: [04] - VIDEO INPUT (R104.1), [05] - HDMI INPUT (C71.1 D6.2 U4.1), [06] - HDMI OUTPUT (C22.1 U5.1), [07] - PCIE MINI (FB7.1), [09] - USB (6 pins), [03] - CONNECTORS (C15.1 C16.1 J1.76 J1.84), [14] - PWR 5V, 3V3, 2V5 (10 pins)
+5V_HDMI_IN_CON: [04] - VIDEO INPUT (R174.1), [05] - HDMI INPUT (6 pins)
+VIN: [15] - PWR IN, LEDS, BUTTONS, MECH (C381.1 D1.3 TP9.1), [04] - VIDEO INPUT (5 pins), [07] - PCIE MINI (5 pins), [09] - USB (FB12.1), [03] - CONNECTORS (19 pins), [14] - PWR 5V, 3V3, 2V5 (18 pins)
GND: [15] - PWR IN, LEDS, BUTTONS, MECH (29 pins), [04] - VIDEO INPUT (48 pins), [05] - HDMI INPUT (25 pins), [06] - HDMI OUTPUT (28 pins), [07] - PCIE MINI (47 pins), [09] - USB (42 pins), [08] - ETHERNET (8 pins), [03] - CONNECTORS (74 pins), [10] - SATA, CSI (13 pins), [11] - SD CARD, BUFFERS (11 pins), [12] - UARTS (11 pins), [13] - HEADERS, SPI (12 pins), [14] - PWR 5V, 3V3, 2V5 (53 pins)
AUD4_CLK: [04] - VIDEO INPUT (R167.2), [03] - CONNECTORS (J2.14)
AUD4_RXD: [04] - VIDEO INPUT (R169.2), [03] - CONNECTORS (J2.22)
AUD4_TXC: [04] - VIDEO INPUT (R166.2), [03] - CONNECTORS (J2.16)
AUD4_TXFS: [04] - VIDEO INPUT (R168.2), [03] - CONNECTORS (J2.18)
BOOT_MODE0_CON: [09] - USB (U14.1), [03] - CONNECTORS (J2.3), [13] - HEADERS, SPI (JP1.1)
BUF_SYS_RSTn: [07] - PCIE MINI (J13.22), [09] - USB (R155.2), [11] - SD CARD, BUFFERS (R64.2 U20.4), [13] - HEADERS, SPI (J19.8)
CPU_GPIO0: [03] - CONNECTORS (R43.2), [13] - HEADERS, SPI (J19.10)
CPU_GPIO1: [03] - CONNECTORS (J2.15), [13] - HEADERS, SPI (J19.11)
CPU_GPIO2: [03] - CONNECTORS (J3.50), [13] - HEADERS, SPI (J18.5)
CPU_GPIO3: [03] - CONNECTORS (J3.56), [13] - HEADERS, SPI (J18.6)
CPU_GPIO4: [03] - CONNECTORS (J3.60), [13] - HEADERS, SPI (J18.7)
CPU_GPIO5: [03] - CONNECTORS (J3.62), [13] - HEADERS, SPI (J18.8)
CPU_GPIO6: [03] - CONNECTORS (J3.64), [13] - HEADERS, SPI (J18.9)
CPU_GPIO7: [03] - CONNECTORS (J3.66), [13] - HEADERS, SPI (J18.10)
CSI1_GPIO: [03] - CONNECTORS (J3.19), [10] - SATA, CSI (R34.2)
CSI1_PIXCLK_R: [03] - CONNECTORS (R35.2 R42.2), [10] - SATA, CSI (J12.12)
CSI_CLK0_N: [03] - CONNECTORS (J2.86), [10] - SATA, CSI (J12.8)
CSI_CLK0_P: [03] - CONNECTORS (J2.88), [10] - SATA, CSI (J12.9)
CSI_D0_N: [03] - CONNECTORS (J2.92), [10] - SATA, CSI (J12.2)
CSI_D0_P: [03] - CONNECTORS (J2.94), [10] - SATA, CSI (J12.3)
CSI_D1_N: [03] - CONNECTORS (J2.98), [10] - SATA, CSI (J12.5)
CSI_D1_P: [03] - CONNECTORS (J2.100), [10] - SATA, CSI (J12.6)
CSPI1_CLK: [03] - CONNECTORS (J2.23), [13] - HEADERS, SPI (U8.6)
CSPI1_CS0: [03] - CONNECTORS (J2.29), [13] - HEADERS, SPI (U8.1)
CSPI1_MISO: [03] - CONNECTORS (J2.27), [13] - HEADERS, SPI (U8.2)
CSPI1_MOSI: [03] - CONNECTORS (J2.25), [13] - HEADERS, SPI (U8.5)
CSPI2_CLK: [03] - CONNECTORS (J3.70), [13] - HEADERS, SPI (J17.1)
CSPI2_CS0: [03] - CONNECTORS (J3.76), [13] - HEADERS, SPI (J17.5)
CSPI2_CS1: [03] - CONNECTORS (J3.78), [13] - HEADERS, SPI (J17.6)
CSPI2_MISO: [03] - CONNECTORS (J3.74), [13] - HEADERS, SPI (J17.3)
CSPI2_MOSI: [03] - CONNECTORS (J3.72), [13] - HEADERS, SPI (J17.4)
ENET_LED_LINK: [08] - ETHERNET (J5.11), [03] - CONNECTORS (J3.14)
ENET_LED_RX: [08] - ETHERNET (J5.9), [03] - CONNECTORS (J3.16)
FLEXCAN1_RX: [03] - CONNECTORS (J2.32), [13] - HEADERS, SPI (J17.8)
FLEXCAN1_TX: [03] - CONNECTORS (J2.30), [13] - HEADERS, SPI (J17.9)
GPIO_OR_PWM_1: [03] - CONNECTORS (J2.17), [13] - HEADERS, SPI (J19.13)
GPIO_OR_PWM_2: [03] - CONNECTORS (J2.19), [13] - HEADERS, SPI (J19.14)
GPIO_OR_PWM_3: [03] - CONNECTORS (J3.52), [13] - HEADERS, SPI (J18.1)
GPIO_OR_PWM_4: [03] - CONNECTORS (J3.54), [13] - HEADERS, SPI (J18.2)
HDMI_IN_CEC_IN: [04] - VIDEO INPUT (R105.1), [05] - HDMI INPUT (R12.1 U4.16)
HDMI_IN_CLK_N: [04] - VIDEO INPUT (U1.C2), [05] - HDMI INPUT (J11.14 U4.15 U4.24)
HDMI_IN_CLK_P: [04] - VIDEO INPUT (U1.C1), [05] - HDMI INPUT (J11.12 U4.13 U4.26)
HDMI_IN_D0_N: [04] - VIDEO INPUT (U1.D2), [05] - HDMI INPUT (J11.11 U4.12 U4.27)
HDMI_IN_D0_P: [04] - VIDEO INPUT (U1.D1), [05] - HDMI INPUT (J11.9 U4.10 U4.29)
HDMI_IN_D1_N: [04] - VIDEO INPUT (U1.E2), [05] - HDMI INPUT (J11.8 U4.9 U4.30)
HDMI_IN_D1_P: [04] - VIDEO INPUT (U1.E1), [05] - HDMI INPUT (J11.6 U4.7 U4.32)
HDMI_IN_D2_N: [04] - VIDEO INPUT (U1.F2), [05] - HDMI INPUT (J11.5 U4.6 U4.33)
HDMI_IN_D2_P: [04] - VIDEO INPUT (U1.F1), [05] - HDMI INPUT (J11.3 U4.4 U4.35)
HDMI_IN_HPD: [04] - VIDEO INPUT (R165.1), [05] - HDMI INPUT (R13.1 U4.19)
HDMI_OUT_CEC_IN: [06] - HDMI OUTPUT (U5.16), [03] - CONNECTORS (J1.80)
HDMI_OUT_CLK_N: [06] - HDMI OUTPUT (J6.12 U5.15 U5.24), [03] - CONNECTORS (J1.92)
HDMI_OUT_CLK_P: [06] - HDMI OUTPUT (J6.10 U5.13 U5.26), [03] - CONNECTORS (J1.94)
HDMI_OUT_D0_N: [06] - HDMI OUTPUT (J6.9 U5.12 U5.27), [03] - CONNECTORS (J1.86)
HDMI_OUT_D0_P: [06] - HDMI OUTPUT (J6.7 U5.10 U5.29), [03] - CONNECTORS (J1.88)
HDMI_OUT_D1_N: [06] - HDMI OUTPUT (J6.6 U5.9 U5.30), [03] - CONNECTORS (J1.79)
HDMI_OUT_D1_P: [06] - HDMI OUTPUT (J6.4 U5.7 U5.32), [03] - CONNECTORS (J1.81)
HDMI_OUT_D2_N: [06] - HDMI OUTPUT (J6.3 U5.6 U5.33), [03] - CONNECTORS (J1.85)
HDMI_OUT_D2_P: [06] - HDMI OUTPUT (J6.1 U5.4 U5.35), [03] - CONNECTORS (J1.87)
HDMI_OUT_HPD: [06] - HDMI OUTPUT (R41.2 U3.4), [03] - CONNECTORS (J1.78)
I2C1_SCL: [06] - HDMI OUTPUT (U5.17), [03] - CONNECTORS (J2.26), [13] - HEADERS, SPI (J19.1)
I2C1_SDA: [06] - HDMI OUTPUT (U5.18), [03] - CONNECTORS (J2.28), [13] - HEADERS, SPI (J19.2)
I2C2_DDC_SCL: [04] - VIDEO INPUT (R6.1 R9.2 U1.A3), [05] - HDMI INPUT (U4.17)
I2C2_DDC_SDA: [04] - VIDEO INPUT (R7.1 R8.2 U1.B3), [05] - HDMI INPUT (U4.18)
I2C2_SCL: [04] - VIDEO INPUT (R9.1), [07] - PCIE MINI (J13.30), [03] - CONNECTORS (J2.48), [10] - SATA, CSI (R135.2), [13] - HEADERS, SPI (J17.11)
I2C2_SDA: [04] - VIDEO INPUT (R8.1), [07] - PCIE MINI (J13.32), [03] - CONNECTORS (J2.50), [10] - SATA, CSI (R136.2), [13] - HEADERS, SPI (J17.10)
I2C3_SCL: [04] - VIDEO INPUT (U1.B8), [03] - CONNECTORS (J2.54), [13] - HEADERS, SPI (J17.14)
I2C3_SDA: [04] - VIDEO INPUT (U1.B7), [03] - CONNECTORS (J2.52), [13] - HEADERS, SPI (J17.13)
MPCIE_WDISn: [07] - PCIE MINI (R22.2), [03] - CONNECTORS (J1.40)
PCIE_CLK_N: [07] - PCIE MINI (J13.11), [03] - CONNECTORS (J2.80)
PCIE_CLK_P: [07] - PCIE MINI (J13.13), [03] - CONNECTORS (J2.82)
PCIE_RX_N: [07] - PCIE MINI (J13.23), [03] - CONNECTORS (J2.85)
PCIE_RX_P: [07] - PCIE MINI (J13.25), [03] - CONNECTORS (J2.87)
PCIE_TX_N: [07] - PCIE MINI (J13.31), [03] - CONNECTORS (J2.79)
PCIE_TX_P: [07] - PCIE MINI (J13.33), [03] - CONNECTORS (J2.81)
PCIE_WAKE: [07] - PCIE MINI (J13.1 R37.1), [03] - CONNECTORS (J2.76)
POK_1V5_MODULE: [03] - CONNECTORS (J2.5), [14] - PWR 5V, 3V3, 2V5 (R31.1 R220.1)
POK_1V8: [04] - VIDEO INPUT (R5.1 R81.1 U2.3), [07] - PCIE MINI (U6.5)
POK_3V3: [04] - VIDEO INPUT (U2.5), [03] - CONNECTORS (J2.9), [14] - PWR 5V, 3V3, 2V5 (U10.14)
POK_5V: [03] - CONNECTORS (J2.7), [14] - PWR 5V, 3V3, 2V5 (R26.1 U9.14)
POKn: [15] - PWR IN, LEDS, BUTTONS, MECH (Q4.1), [04] - VIDEO INPUT (R5.2), [07] - PCIE MINI (R153.2), [11] - SD CARD, BUFFERS (R117.1 U21.1)
PWR_JACK_INSERTn: [15] - PWR IN, LEDS, BUTTONS, MECH (J7.3), [09] - USB (R63.1)
PWR_LED_HDR: [15] - PWR IN, LEDS, BUTTONS, MECH (R144.1), [13] - HEADERS, SPI (J19.7)
RST_BTN_HDR: [15] - PWR IN, LEDS, BUTTONS, MECH (R140.1 R141.2 SW1.2), [13] - HEADERS, SPI (J19.6)
RST_BTNn: [15] - PWR IN, LEDS, BUTTONS, MECH (C198.1 R141.1), [11] - SD CARD, BUFFERS (U21.2)
SATA_RX_N: [03] - CONNECTORS (J2.36), [10] - SATA, CSI (J9.5)
SATA_RX_P: [03] - CONNECTORS (J2.38), [10] - SATA, CSI (J9.6)
SATA_TX_N: [03] - CONNECTORS (J2.42), [10] - SATA, CSI (J9.3)
SATA_TX_P: [03] - CONNECTORS (J2.44), [10] - SATA, CSI (J9.2)
SD3_CD: [03] - CONNECTORS (J2.33), [11] - SD CARD, BUFFERS (Q3.3)
SD3_CLK: [03] - CONNECTORS (J2.37), [11] - SD CARD, BUFFERS (J15.5)
SD3_CMD: [03] - CONNECTORS (J2.39), [11] - SD CARD, BUFFERS (J15.3)
SD3_DATA0: [03] - CONNECTORS (J2.43), [11] - SD CARD, BUFFERS (J15.7)
SD3_DATA1: [03] - CONNECTORS (J2.45), [11] - SD CARD, BUFFERS (J15.8)
SD3_DATA2: [03] - CONNECTORS (J2.47), [11] - SD CARD, BUFFERS (J15.1)
SD3_DATA3: [03] - CONNECTORS (J2.49), [11] - SD CARD, BUFFERS (J15.2)
SD3_WP: [03] - CONNECTORS (J2.35), [11] - SD CARD, BUFFERS (R139.2)
SYS_POKn: [03] - CONNECTORS (J2.2), [11] - SD CARD, BUFFERS (U21.4)
SYS_RSTn: [03] - CONNECTORS (J2.4), [11] - SD CARD, BUFFERS (U20.1 U20.2)
TRD0_N: [08] - ETHERNET (T1.12), [03] - CONNECTORS (J3.1)
TRD0_P: [08] - ETHERNET (T1.11), [03] - CONNECTORS (J3.3)
TRD1_N: [08] - ETHERNET (T1.6), [03] - CONNECTORS (J3.7)
TRD1_P: [08] - ETHERNET (T1.5), [03] - CONNECTORS (J3.9)
TRD2_N: [08] - ETHERNET (T1.9), [03] - CONNECTORS (J3.2)
TRD2_P: [08] - ETHERNET (T1.8), [03] - CONNECTORS (J3.4)
TRD3_N: [08] - ETHERNET (T1.3), [03] - CONNECTORS (J3.8)
TRD3_P: [08] - ETHERNET (T1.2), [03] - CONNECTORS (J3.10)
UART1_CTS: [03] - CONNECTORS (J2.59), [12] - UARTS (Q6.1 R56.1 R60.1)
UART1_RTS: [03] - CONNECTORS (J2.57), [12] - UARTS (Q8.4 R61.1 R71.1)
UART1_RXD: [03] - CONNECTORS (J2.55), [12] - UARTS (Q8.1 R54.1 R58.1)
UART1_TXD: [03] - CONNECTORS (J2.53), [12] - UARTS (Q6.4 R59.1 R70.1)
UART2_RXD: [03] - CONNECTORS (J2.63), [12] - UARTS (J16.2)
UART2_TXD: [03] - CONNECTORS (J2.61), [12] - UARTS (J16.1)
UART3_CTS: [03] - CONNECTORS (J3.77), [12] - UARTS (J16.12)
UART3_RTS: [03] - CONNECTORS (J3.75), [12] - UARTS (J16.11)
UART3_RXD: [03] - CONNECTORS (J3.73), [12] - UARTS (J16.13)
UART3_TXD: [03] - CONNECTORS (J3.71), [12] - UARTS (J16.14)
UART4_RXD: [03] - CONNECTORS (J2.60), [12] - UARTS (J16.5)
UART4_TXD: [03] - CONNECTORS (J2.58), [12] - UARTS (J16.6)
UART5_RXD: [03] - CONNECTORS (J2.64), [12] - UARTS (J16.8)
UART5_TXD: [03] - CONNECTORS (J2.62), [12] - UARTS (J16.9)
USB0_ID: [09] - USB (5 pins), [03] - CONNECTORS (J2.68)
USB0_ID_BUFF_EN: [09] - USB (R67.2 R304.2), [03] - CONNECTORS (J1.38)
USB0_N: [09] - USB (U12.7), [03] - CONNECTORS (J2.73)
USB0_P: [09] - USB (U12.8), [03] - CONNECTORS (J2.75)
USB0_PWR_EN: [09] - USB (5 pins), [03] - CONNECTORS (J2.74)
USB1_N: [09] - USB (U13.7), [03] - CONNECTORS (J2.67)
USB1_P: [09] - USB (U13.8), [03] - CONNECTORS (J2.69)
USB1_PWR_EN: [09] - USB (5 pins), [03] - CONNECTORS (J2.72)
USB_MPCIE_N: [07] - PCIE MINI (L6.3), [09] - USB (U13.2)
USB_MPCIE_P: [07] - PCIE MINI (L6.4), [09] - USB (U13.1)
USB_OC: [09] - USB (U7.2 U7.3), [03] - CONNECTORS (J2.70)
USER_BTN_HDR: [15] - PWR IN, LEDS, BUTTONS, MECH (R147.1 R149.2 SW2.2), [13] - HEADERS, SPI (J19.4)
USER_BUTTON: [15] - PWR IN, LEDS, BUTTONS, MECH (C200.1 R149.1), [03] - CONNECTORS (J2.10)
USER_LED_BB: [15] - PWR IN, LEDS, BUTTONS, MECH (Q5.1), [03] - CONNECTORS (J1.82)
USER_LED_HDR: [15] - PWR IN, LEDS, BUTTONS, MECH (R148.1), [13] - HEADERS, SPI (J19.5)
VID_IN_CSI0_D0: [04] - VIDEO INPUT (R1.2 TP2.1), [03] - CONNECTORS (J1.48)
VID_IN_CSI0_D1: [04] - VIDEO INPUT (R2.2 TP3.1), [03] - CONNECTORS (J1.50)
VID_IN_CSI0_D2: [04] - VIDEO INPUT (U1.F10), [03] - CONNECTORS (J1.52)
VID_IN_CSI0_D3: [04] - VIDEO INPUT (U1.G9), [03] - CONNECTORS (J1.54)
VID_IN_CSI0_D4: [04] - VIDEO INPUT (U1.G10), [03] - CONNECTORS (J1.51)
VID_IN_CSI0_D5: [04] - VIDEO INPUT (U1.H9), [03] - CONNECTORS (J1.53)
VID_IN_CSI0_D6: [04] - VIDEO INPUT (U1.H10), [03] - CONNECTORS (J1.55)
VID_IN_CSI0_D7: [04] - VIDEO INPUT (U1.J9), [03] - CONNECTORS (J1.57)
VID_IN_CSI0_D8: [04] - VIDEO INPUT (U1.K9), [03] - CONNECTORS (J1.58)
VID_IN_CSI0_D9: [04] - VIDEO INPUT (U1.J8), [03] - CONNECTORS (J1.60)
VID_IN_CSI0_D10: [04] - VIDEO INPUT (R3.2 TP5.1), [03] - CONNECTORS (J1.62)
VID_IN_CSI0_D11: [04] - VIDEO INPUT (R4.2 TP6.1), [03] - CONNECTORS (J1.64)
VID_IN_CSI0_D12: [04] - VIDEO INPUT (U1.K8), [03] - CONNECTORS (J1.61)
VID_IN_CSI0_D13: [04] - VIDEO INPUT (U1.J7), [03] - CONNECTORS (J1.63)
VID_IN_CSI0_D14: [04] - VIDEO INPUT (U1.K7), [03] - CONNECTORS (J1.65)
VID_IN_CSI0_D15: [04] - VIDEO INPUT (U1.J6), [03] - CONNECTORS (J1.67)
VID_IN_CSI0_D16: [04] - VIDEO INPUT (U1.K6), [03] - CONNECTORS (J1.68)
VID_IN_CSI0_D17: [04] - VIDEO INPUT (U1.J5), [03] - CONNECTORS (J1.70)
VID_IN_CSI0_D18: [04] - VIDEO INPUT (U1.K5), [03] - CONNECTORS (J1.72)
VID_IN_CSI0_D19: [04] - VIDEO INPUT (U1.J4), [03] - CONNECTORS (J1.74)
VID_IN_CSI0_DE: [04] - VIDEO INPUT (U1.E10), [03] - CONNECTORS (J1.75)
VID_IN_CSI0_HS: [04] - VIDEO INPUT (U1.F9), [03] - CONNECTORS (J1.47)
VID_IN_CSI0_INT: [04] - VIDEO INPUT (R109.1), [03] - CONNECTORS (J1.73)
VID_IN_CSI0_PIXCLK: [04] - VIDEO INPUT (R66.1), [03] - CONNECTORS (J1.43)
VID_IN_CSI0_RSTn: [04] - VIDEO INPUT (U1.B6), [03] - CONNECTORS (J1.71)
VID_IN_CSI0_VS: [04] - VIDEO INPUT (U1.E9), [03] - CONNECTORS (J1.45)

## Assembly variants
Production: not fitted C21 C59 C92 C263 C264 D2 D4 D8 D12 D13 D15 FB1 FB2 FB12 FB24 R5 R6 R7 R10 R14 R25 R29 R32 R37 R38 R39 R41 R42 R45 R53 R58 R59 R60 R61 R62 R63 R67 R70 R71 R104 R166 R167 R168 R169 R220 R247 R304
